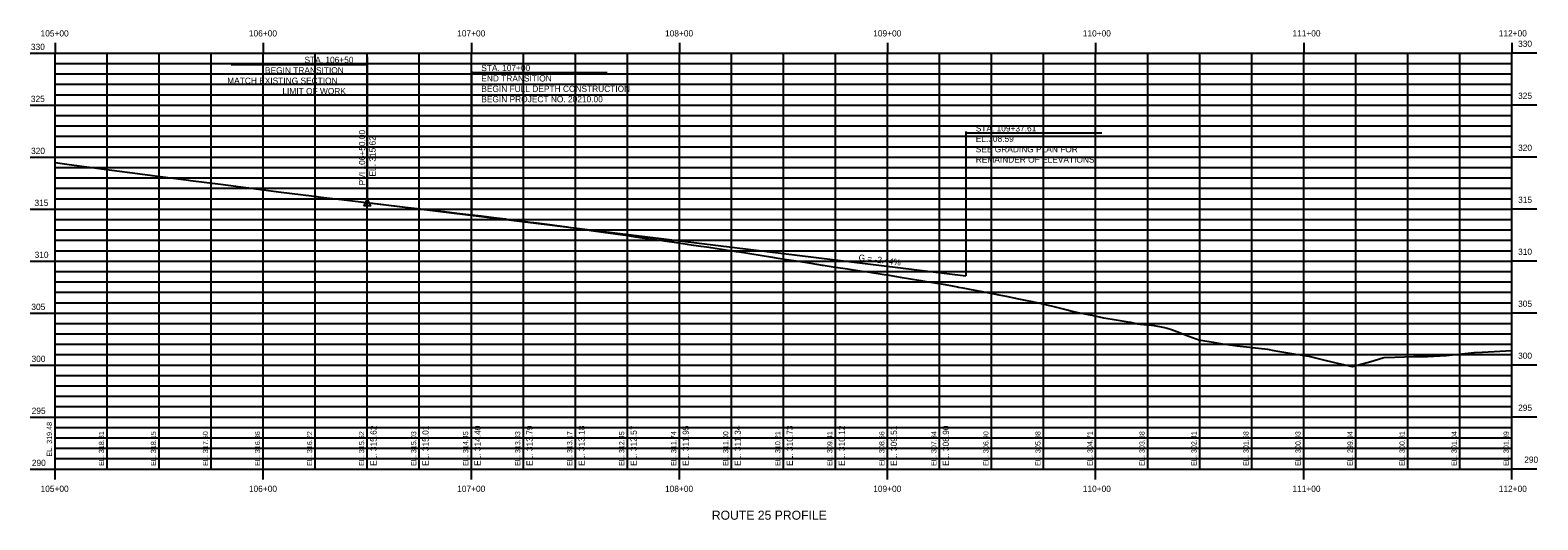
# Model space of a CAD drawing. Extents: x 916064 to 2216531, y 210276 to 327856.
# Drawn here: x 916064 to 916789, y 327621 to 327856 of the extents above; entities that cross this region are included whole.
import ezdxf

# ---------------------------------------------------------------- set-up
doc = ezdxf.new("R2010")
doc.units = 0
for name, color, linetype in [('ANNOTATION', 7, 'Continuous'), ('BARRIER', 7, 'Continuous'), ('D_Roadway_Centerline', 7, 'Continuous'), ('D_Roadway_Centerline_Bearings', 7, 'Continuous'), ('D_Roadway_Centerline_CurveData', 7, 'Continuous'), ('D_Roadway_Centerline_Flags', 7, 'Continuous'), ('D_Roadway_Centerline_Text', 7, 'Continuous'), ('D_Roadway_Edge_Pavement', 7, 'Continuous')]:
    doc.layers.add(name, color=color, linetype=linetype)

msp = doc.modelspace()

# ---------------------------------------------------------------- linework, layer by layer
at = {"layer": 'ANNOTATION'}
msp.add_line((916226.5, 327773.51), (916514.11, 327738.37), dxfattribs=at)
at = {"layer": 'D_Roadway_Centerline'}
for p, q in [((916076.5, 327850.41), (916076.5, 327845.41)), ((916176.5, 327850.41), (916176.5, 327845.41)), ((916276.5, 327850.41), (916276.5, 327845.41)), ((916376.5, 327850.41), (916376.5, 327845.41)), ((916476.5, 327850.41), (916476.5, 327845.41)), ((916576.5, 327850.41), (916576.5, 327845.41)), ((916676.5, 327850.41), (916676.5, 327845.41)), ((916776.5, 327850.41), (916776.5, 327845.41)), ((916064.5, 327845.41), (916076.5, 327845.41)), ((916064.5, 327845.41), (916076.5, 327845.41)), ((916076.5, 327845.41), (916776.5, 327845.41)), ((916076.5, 327645.41), (916076.5, 327845.41)), ((916176.5, 327645.41), (916176.5, 327845.41)), ((916276.5, 327645.41), (916276.5, 327845.41)), ((916376.5, 327645.41), (916376.5, 327845.41)), ((916476.5, 327645.41), (916476.5, 327845.41)), ((916576.5, 327645.41), (916576.5, 327845.41)), ((916676.5, 327645.41), (916676.5, 327845.41)), ((916776.5, 327645.41), (916776.5, 327845.41)), ((916788.5, 327845.41), (916776.5, 327845.41)), ((916788.5, 327845.41), (916776.5, 327845.41)), ((916064.5, 327820.41), (916076.5, 327820.41)), ((916076.5, 327820.41), (916776.5, 327820.41)), ((916788.5, 327820.41), (916776.5, 327820.41)), ((916064.5, 327795.41), (916076.5, 327795.41)), ((916076.5, 327795.41), (916776.5, 327795.41)), ((916788.5, 327795.41), (916776.5, 327795.41)), ((916064.5, 327770.41), (916076.5, 327770.41)), ((916076.5, 327770.41), (916776.5, 327770.41)), ((916788.5, 327770.41), (916776.5, 327770.41)), ((916064.5, 327745.41), (916076.5, 327745.41)), ((916076.5, 327745.41), (916776.5, 327745.41)), ((916788.5, 327745.41), (916776.5, 327745.41)), ((916064.5, 327720.41), (916076.5, 327720.41)), ((916076.5, 327720.41), (916776.5, 327720.41)), ((916788.5, 327720.41), (916776.5, 327720.41)), ((916064.5, 327695.41), (916076.5, 327695.41)), ((916076.5, 327695.41), (916776.5, 327695.41)), ((916788.5, 327695.41), (916776.5, 327695.41)), ((916064.5, 327670.41), (916076.5, 327670.41)), ((916076.5, 327670.41), (916776.5, 327670.41)), ((916788.5, 327670.41), (916776.5, 327670.41)), ((916064.5, 327645.41), (916076.5, 327645.41)), ((916076.5, 327645.41), (916776.5, 327645.41)), ((916076.5, 327640.42), (916076.5, 327645.41)), ((916176.5, 327640.42), (916176.5, 327645.41)), ((916276.5, 327640.42), (916276.5, 327645.41)), ((916376.5, 327640.42), (916376.5, 327645.41)), ((916476.5, 327640.42), (916476.5, 327645.41)), ((916576.5, 327640.42), (916576.5, 327645.41)), ((916676.5, 327640.42), (916676.5, 327645.41)), ((916788.5, 327645.41), (916776.5, 327645.41)), ((916776.5, 327640.42), (916776.5, 327645.41))]:
    msp.add_line(p, q, dxfattribs=at)
at = {"layer": 'D_Roadway_Centerline_Bearings'}
msp.add_line((916226.5, 327773.51), (916226.5, 327821.11), dxfattribs=at)
msp.add_lwpolyline([(916226.5, 327775.01), (916228, 327772.01), (916225, 327772.01)], close=True, dxfattribs=at)
at = {"layer": 'D_Roadway_Centerline_Flags'}
msp.add_lwpolyline([(916076.5, 327792.82), (916083.32, 327791.91), (916097.86, 327789.95), (916098.75, 327789.83), (916107.37, 327788.66), (916107.44, 327788.65), (916112.4, 327788), (916126.93, 327786.09), (916138.26, 327784.6), (916138.51, 327784.57), (916141.47, 327784.19), (916156.01, 327782.33), (916169.43, 327780.6), (916169.53, 327780.59), (916170.55, 327780.46), (916185.08, 327778.61), (916199.62, 327776.75), (916201.67, 327776.48), (916202.27, 327776.4), (916202.28, 327776.4), (916202.82, 327776.34), (916214.16, 327774.99), (916228.7, 327773.25), (916232.69, 327772.77), (916243.23, 327771.55), (916257.77, 327769.85), (916261.72, 327769.39), (916262.39, 327769.31), (916263.64, 327769.17), (916269.51, 327768.49), (916275.37, 327767.79), (916281.24, 327767.09), (916287.11, 327766.38), (916292.97, 327765.66), (916293.24, 327765.63), (916293.72, 327765.57), (916298.84, 327764.93), (916304.71, 327764.18), (916306.46, 327763.95), (916310.58, 327763.41), (916316.44, 327762.62), (916322.31, 327761.82), (916324.07, 327761.57), (916325.57, 327761.37), (916328.18, 327761.01), (916334.04, 327760.19), (916339.91, 327759.35), (916345.78, 327758.51), (916351.65, 327757.64), (916353.35, 327757.39), (916357.51, 327756.76), (916358.64, 327756.59), (916363.38, 327755.94), (916369.25, 327755.12), (916375.12, 327754.29), (916380.27, 327753.55), (916380.98, 327753.45), (916386.85, 327752.62), (916389.49, 327752.23), (916392.72, 327751.75), (916398.58, 327750.86), (916403.75, 327750.07), (916404.45, 327749.96), (916410.32, 327749.03), (916416.19, 327748.1), (916421.14, 327747.29), (916422.05, 327747.15), (916427.92, 327746.24), (916433.79, 327745.31), (916439.65, 327744.37), (916445.04, 327743.5), (916445.52, 327743.42), (916451.39, 327742.47), (916451.44, 327742.46), (916457.26, 327741.62), (916463.12, 327740.76), (916468.06, 327740.02), (916468.99, 327739.88), (916474.86, 327738.98), (916476.35, 327738.74), (916480.73, 327738.01), (916482.5, 327737.71), (916486.59, 327737.05), (916492.46, 327736.1), (916494.27, 327735.8), (916498.33, 327735.13), (916504.19, 327734.14), (916507.49, 327733.58), (916510.06, 327733.04), (916510.59, 327732.93), (916512.7, 327732.51), (916515.93, 327731.91), (916521.8, 327730.81), (916527.66, 327729.68), (916529.96, 327729.23), (916533.53, 327728.52), (916539.4, 327727.33), (916543.42, 327726.49), (916543.42, 327726.46), (916545.27, 327726.11), (916547.51, 327725.67), (916551.13, 327724.88), (916552.4, 327724.59), (916557, 327723.44), (916562.87, 327721.95), (916565.87, 327721.16), (916568.73, 327720.59), (916574.6, 327719.37), (916580.33, 327718.17), (916580.47, 327718.14), (916586.3, 327717.13), (916592.12, 327716.14), (916593.17, 327715.96), (916596.63, 327715.28), (916597.95, 327715.15), (916603.34, 327714.63), (916603.78, 327714.54), (916609.61, 327713.42), (916610.89, 327713.19), (916612.88, 327712.5), (916615.44, 327711.51), (916621.26, 327709.35), (916626.63, 327707.44), (916627.09, 327707.36), (916632.92, 327706.36), (916636.36, 327705.81), (916638.75, 327705.46), (916644.57, 327704.67), (916650.4, 327703.96), (916656.23, 327703.31), (916657.83, 327703.16), (916659.07, 327703.03), (916662.06, 327702.47), (916667.88, 327701.44), (916673.71, 327700.48), (916678.97, 327699.68), (916678.99, 327699.68), (916679, 327699.67), (916679.24, 327699.61), (916679.54, 327699.54), (916685.37, 327698.13), (916691.2, 327696.72), (916697.02, 327695.33), (916698.99, 327694.86), (916699.87, 327694.66), (916699.9, 327694.66), (916702.85, 327695.49), (916708.68, 327697.17), (916714.51, 327698.88), (916715.13, 327699.06), (916720.33, 327699.23), (916729.35, 327699.55), (916735.94, 327699.56), (916745.16, 327699.93), (916758.44, 327701.41), (916758.63, 327701.44), (916762.21, 327701.65), (916776.45, 327702.34), (916776.5, 327702.34)], dxfattribs=at)
at = {"layer": 'D_Roadway_Centerline_Text'}
for p, q in [((916101.5, 327645.41), (916101.5, 327845.41)), ((916126.5, 327645.41), (916126.5, 327845.41)), ((916151.5, 327645.41), (916151.5, 327845.41)), ((916201.5, 327645.41), (916201.5, 327845.41)), ((916226.5, 327645.41), (916226.5, 327845.41)), ((916251.5, 327645.41), (916251.5, 327845.41)), ((916301.5, 327645.41), (916301.5, 327845.41)), ((916326.5, 327645.41), (916326.5, 327845.41)), ((916351.5, 327645.41), (916351.5, 327845.41)), ((916401.5, 327645.41), (916401.5, 327845.41)), ((916426.5, 327645.41), (916426.5, 327845.41)), ((916451.5, 327645.41), (916451.5, 327845.41)), ((916501.5, 327645.41), (916501.5, 327845.41)), ((916526.5, 327645.41), (916526.5, 327845.41)), ((916551.5, 327645.41), (916551.5, 327845.41)), ((916601.5, 327645.41), (916601.5, 327845.41)), ((916626.5, 327645.41), (916626.5, 327845.41)), ((916651.5, 327645.41), (916651.5, 327845.41)), ((916701.5, 327645.41), (916701.5, 327845.41)), ((916726.5, 327645.41), (916726.5, 327845.41)), ((916751.5, 327645.41), (916751.5, 327845.41)), ((916076.5, 327840.41), (916776.5, 327840.41)), ((916076.5, 327835.41), (916776.5, 327835.41)), ((916076.5, 327830.41), (916776.5, 327830.41)), ((916076.5, 327825.41), (916776.5, 327825.41)), ((916076.5, 327815.41), (916776.5, 327815.41)), ((916076.5, 327810.41), (916776.5, 327810.41)), ((916076.5, 327805.41), (916776.5, 327805.41)), ((916076.5, 327800.41), (916776.5, 327800.41)), ((916076.5, 327790.41), (916776.5, 327790.41)), ((916076.5, 327785.41), (916776.5, 327785.41)), ((916076.5, 327780.41), (916776.5, 327780.41)), ((916076.5, 327775.41), (916776.5, 327775.41)), ((916076.5, 327765.41), (916776.5, 327765.41)), ((916076.5, 327760.41), (916776.5, 327760.41)), ((916076.5, 327755.41), (916776.5, 327755.41)), ((916076.5, 327750.41), (916776.5, 327750.41)), ((916076.5, 327740.41), (916776.5, 327740.41)), ((916076.5, 327735.41), (916776.5, 327735.41)), ((916076.5, 327730.41), (916776.5, 327730.41)), ((916076.5, 327725.41), (916776.5, 327725.41)), ((916076.5, 327715.41), (916776.5, 327715.41)), ((916076.5, 327710.41), (916776.5, 327710.41)), ((916076.5, 327705.41), (916776.5, 327705.41)), ((916076.5, 327700.41), (916776.5, 327700.41)), ((916076.5, 327690.41), (916776.5, 327690.41)), ((916076.5, 327685.41), (916776.5, 327685.41)), ((916076.5, 327680.41), (916776.5, 327680.41)), ((916076.5, 327675.41), (916776.5, 327675.41)), ((916076.5, 327665.41), (916776.5, 327665.41)), ((916076.5, 327660.41), (916776.5, 327660.41)), ((916076.5, 327655.41), (916776.5, 327655.41)), ((916076.5, 327650.41), (916776.5, 327650.41))]:
    msp.add_line(p, q, dxfattribs=at)
at = {"layer": 'D_Roadway_Edge_Pavement'}
for p, q in [((916226.5, 327843.64), (916226.5, 327773.51)), ((916161.16, 327839.86), (916226.5, 327839.86)), ((916276.5, 327836.74), (916276.5, 327767.4)), ((916341.84, 327835.99), (916276.5, 327835.99)), ((916514.11, 327807.7), (916514.11, 327738.37)), ((916579.45, 327806.95), (916514.11, 327806.95))]:
    msp.add_line(p, q, dxfattribs=at)

# ---------------------------------------------------------------- texts
at = {"layer": 'BARRIER'}
for s, p in [('EL. 315.62', (916231, 327646.91)), ('EL. 315.01', (916256, 327646.91)), ('EL. 314.40', (916281, 327646.91)), ('EL. 313.79', (916306, 327646.91)), ('EL. 313.18', (916331, 327646.91)), ('EL. 312.57', (916356, 327646.91)), ('EL. 311.95', (916381, 327646.91)), ('EL. 311.34', (916406, 327646.91)), ('EL. 310.73', (916431, 327646.91)), ('EL. 310.12', (916456, 327646.91)), ('EL. 309.51', (916481, 327646.91)), ('EL. 308.90', (916506, 327646.91))]:
    msp.add_text(s, height=3, rotation=90, dxfattribs=at).set_placement(p)
at = {"layer": 'D_Roadway_Centerline_Bearings'}
for s, rotation, p in [('PVI 106+50.00', 90, (916225.5, 327781.84)), ('EL. 315.62', 90, (916230.5, 327786.06)), ('G = -2.44%', 353.03351, (916462.44, 327745.7))]:
    msp.add_text(s, height=3, rotation=rotation, dxfattribs=at).set_placement(p)
at = {"layer": 'D_Roadway_Centerline_CurveData'}
for s, height, p in [('105+00', 3, (916069.51, 327853.41)), ('106+00', 3, (916169.62, 327853.41)), ('107+00', 3, (916269.7, 327853.41)), ('108+00', 3, (916369.57, 327853.41)), ('109+00', 3, (916469.62, 327853.41)), ('110+00', 3, (916570.32, 327853.41)), ('111+00', 3, (916671.07, 327853.41)), ('112+00', 3, (916770.21, 327853.41)), ('330', 3, (916064.88, 327846.91)), ('330', 3, (916064.88, 327846.91)), ('330', 3, (916779.5, 327848.41)), ('330', 3, (916779.5, 327848.41)), ('325', 3, (916779.5, 327823.41)), ('325', 3, (916064.85, 327821.91)), ('320', 3, (916064.93, 327796.91)), ('320', 3, (916779.5, 327798.41)), ('315', 3, (916779.5, 327773.41)), ('315', 3, (916066.57, 327771.91)), ('310', 3, (916066.65, 327746.91)), ('310', 3, (916779.5, 327748.41)), ('305', 3, (916065.07, 327721.91)), ('305', 3, (916779.5, 327723.41)), ('300', 3, (916065.15, 327696.91)), ('300', 3, (916779.5, 327698.41)), ('295', 3, (916065.23, 327671.91)), ('295', 3, (916779.5, 327673.41)), ('290', 3, (916065.31, 327646.91)), ('290', 3, (916782.45, 327648.41)), ('105+00', 3, (916069.51, 327634.42)), ('106+00', 3, (916169.62, 327634.42)), ('107+00', 3, (916269.7, 327634.42)), ('108+00', 3, (916369.57, 327634.42)), ('109+00', 3, (916469.62, 327634.42)), ('110+00', 3, (916570.32, 327634.42)), ('111+00', 3, (916671.07, 327634.42)), ('112+00', 3, (916770.21, 327634.42)), ('ROUTE 25 PROFILE', 4.3749, (916392.05, 327621.04))]:
    msp.add_text(s, height=height, dxfattribs=at).set_placement(p)
at = {"layer": 'D_Roadway_Edge_Pavement'}
for s, p in [('STA. 106+50', (916196.34, 327840.64)), ('MATCH EXISTING SECTION', (916159.18, 327830.64)), ('BEGIN TRANSITION', (916177.32, 327835.64)), ('STA. 107+00', (916281.27, 327836.76)), ('END TRANSITION', (916281.27, 327831.76)), ('LIMIT OF WORK', (916185.7, 327825.64)), ('BEGIN FULL DEPTH CONSTRUCTION', (916281.27, 327826.76)), ('BEGIN PROJECT NO. 20210.00', (916281.27, 327821.76)), ('STA. 109+37.61', (916518.88, 327807.73)), ('EL.308.59', (916518.88, 327802.73)), ('SEE GRADING PLAN FOR', (916518.88, 327797.73)), ('REMAINDER OF ELEVATIONS', (916518.88, 327792.73))]:
    msp.add_text(s, height=3, dxfattribs=at).set_placement(p)
for s, p in [('EL. 319.48', (916075, 327651.36)), ('EL. 318.81', (916100, 327646.91)), ('EL. 318.15', (916125, 327646.91)), ('EL. 317.50', (916150, 327646.91)), ('EL. 316.86', (916175, 327646.91)), ('EL. 316.22', (916200, 327646.91)), ('EL. 315.62', (916225, 327646.91)), ('EL. 315.03', (916250, 327646.91)), ('EL. 314.45', (916275, 327646.91)), ('EL. 313.83', (916300, 327646.91)), ('EL. 313.17', (916325, 327646.91)), ('EL. 312.45', (916350, 327646.91)), ('EL. 311.74', (916375, 327646.91)), ('EL. 311.00', (916400, 327646.91)), ('EL. 310.21', (916425, 327646.91)), ('EL. 309.41', (916450, 327646.91)), ('EL. 308.66', (916475, 327646.91)), ('EL. 307.84', (916500, 327646.91)), ('EL. 306.90', (916525, 327646.91)), ('EL. 305.88', (916550, 327646.91)), ('EL. 304.71', (916575, 327646.91)), ('EL. 303.88', (916600, 327646.91)), ('EL. 302.41', (916625, 327646.91)), ('EL. 301.68', (916650, 327646.91)), ('EL. 300.93', (916675, 327646.91)), ('EL. 299.94', (916700, 327646.91)), ('EL. 300.81', (916725, 327646.91)), ('EL. 301.04', (916750, 327646.91)), ('EL. 301.39', (916775, 327646.91))]:
    msp.add_text(s, height=2.5, rotation=90, dxfattribs=at).set_placement(p)

doc.saveas('drawing.dxf')
